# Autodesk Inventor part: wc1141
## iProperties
Shininess: 64.0
Length Units: 11272
Angle Units: 11279
Time Units: 11290
Mass Units: 11286
Length Display Precision: 3
Angle Display Precision: 2
Compacted: True
Part Number: wc1141
Document SubType Name: Modeling
Created: 2004-08
Designer: John Blackburn
Manufacturer: Standard
Standards Organization: Custom
Density: 0.0
Volumn: 0.0
Area: 0.0
PropertySet Name: Model Information
Control State: 0
Master: False
Checked Out: False
Author: John Blackburn
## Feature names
1. Base1
